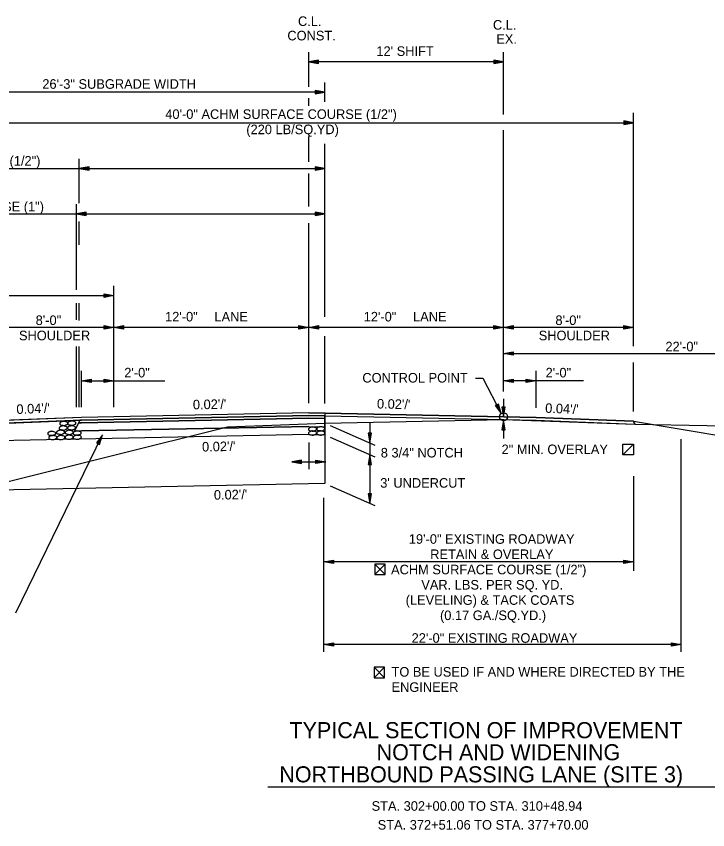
# Model space of a CAD drawing. Extents: x 1398565 to 1398920, y 1968324 to 1968581.
# Drawn here: x 1398824.7 to 1398867.3, y 1968530.5 to 1968580.6 of the extents above; entities that cross this region are included whole.
import ezdxf

# ---------------------------------------------------------------- set-up
doc = ezdxf.new("R2010")
doc.units = 0
for name, color, linetype in [('1', 7, 'Continuous'), ('10', 7, 'Continuous'), ('19', 7, 'Continuous'), ('42', 7, 'Continuous'), ('7', 7, 'Continuous'), ('Level 1', 7, 'Continuous'), ('Level 9', 7, 'Continuous')]:
    doc.layers.add(name, color=color, linetype=linetype)

# ---------------------------------------------------------------- blocks, each defined once
blk = doc.blocks.new('ROCKS')
at = {"layer": '1'}
blk.add_spline([(0.013, 0.06), (0.053, 0.053), (0.107, 0.033), (0.133, 0.013), (0.133, -0.007), (0.12, -0.033), (0.107, -0.04), (0.073, -0.053), (0.033, -0.067), (0.013, -0.067), (-0.02, -0.06), (-0.06, -0.053), (-0.087, -0.047), (-0.113, -0.02), (-0.113, -0.007), (-0.107, 0.02), (-0.087, 0.033), (-0.067, 0.047), (-0.033, 0.053), (-0.02, 0.06), (0.013, 0.06)], degree=3, dxfattribs=at)

msp = doc.modelspace()

# ---------------------------------------------------------------- linework, layer by layer
at = {"layer": '10'}
for p, q in [((1398846.824, 1968546.876), (1398847.465, 1968546.235)), ((1398847.465, 1968546.876), (1398846.824, 1968546.235)), ((1398847.205, 1968546.235), (1398847.216, 1968546.235)), ((1398846.781, 1968540.521), (1398847.422, 1968539.88)), ((1398847.422, 1968540.521), (1398846.781, 1968539.88)), ((1398847.163, 1968539.88), (1398847.174, 1968539.88))]:
    msp.add_line(p, q, dxfattribs=at)
for points in [[(1398862.105, 1968554.258), (1398862.746, 1968554.258), (1398862.746, 1968553.617), (1398862.105, 1968553.617)], [(1398862.105, 1968554.258), (1398862.746, 1968554.258), (1398862.105, 1968553.617)]]:
    msp.add_lwpolyline(points, close=True, dxfattribs=at)
for points in [[(1398847.216, 1968546.235), (1398847.465, 1968546.235), (1398847.465, 1968546.876), (1398846.824, 1968546.876), (1398846.824, 1968546.235), (1398847.205, 1968546.235)], [(1398847.174, 1968539.88), (1398847.422, 1968539.88), (1398847.422, 1968540.521), (1398846.781, 1968540.521), (1398846.781, 1968539.88), (1398847.163, 1968539.88)]]:
    msp.add_lwpolyline(points, dxfattribs=at)
at = {"layer": '19'}
for p, q in [((1398843.353, 1968577.927), (1398842.753, 1968577.822)), ((1398854.753, 1968577.822), (1398842.753, 1968577.822)), ((1398842.753, 1968577.822), (1398843.353, 1968577.717)), ((1398843.353, 1968577.872), (1398842.913, 1968577.837)), ((1398842.913, 1968577.807), (1398843.353, 1968577.767)), ((1398843.353, 1968577.717), (1398843.353, 1968577.927)), ((1398854.153, 1968577.928), (1398854.153, 1968577.718)), ((1398854.753, 1968577.822), (1398854.153, 1968577.928)), ((1398854.593, 1968577.837), (1398854.153, 1968577.873)), ((1398854.153, 1968577.718), (1398854.753, 1968577.822)), ((1398854.153, 1968577.768), (1398854.593, 1968577.807)), ((1398843.753, 1968575.35), (1398843.753, 1968576.547)), ((1398843.753, 1968575.947), (1398817.47, 1968575.947)), ((1398843.153, 1968576.053), (1398843.153, 1968575.843)), ((1398843.753, 1968575.947), (1398843.153, 1968576.053)), ((1398843.593, 1968575.962), (1398843.153, 1968575.998)), ((1398843.153, 1968575.843), (1398843.753, 1968575.947)), ((1398843.153, 1968575.893), (1398843.593, 1968575.932)), ((1398862.753, 1968560.298), (1398862.753, 1968574.672)), ((1398822.753, 1968574.072), (1398862.753, 1968574.072)), ((1398862.153, 1968574.178), (1398862.153, 1968573.968)), ((1398862.753, 1968574.072), (1398862.153, 1968574.178)), ((1398862.593, 1968574.087), (1398862.153, 1968574.123)), ((1398862.153, 1968573.968), (1398862.753, 1968574.072)), ((1398862.153, 1968574.018), (1398862.593, 1968574.057)), ((1398843.753, 1968562.114), (1398843.753, 1968572.76)), ((1398828.626, 1968569.111), (1398828.626, 1968571.85)), ((1398829.226, 1968571.355), (1398828.626, 1968571.25)), ((1398829.226, 1968571.3), (1398828.786, 1968571.265)), ((1398829.226, 1968571.145), (1398829.226, 1968571.355)), ((1398843.153, 1968571.355), (1398843.153, 1968571.145)), ((1398843.753, 1968571.25), (1398843.153, 1968571.355)), ((1398843.593, 1968571.265), (1398843.153, 1968571.3)), ((1398810.228, 1968571.25), (1398843.753, 1968571.25)), ((1398828.626, 1968571.25), (1398829.226, 1968571.145)), ((1398828.786, 1968571.235), (1398829.226, 1968571.195)), ((1398843.153, 1968571.145), (1398843.753, 1968571.25)), ((1398843.153, 1968571.195), (1398843.593, 1968571.235)), ((1398828.455, 1968563.783), (1398828.455, 1968569.052)), ((1398811.73, 1968568.452), (1398843.753, 1968568.452)), ((1398829.055, 1968568.557), (1398828.455, 1968568.452)), ((1398828.455, 1968568.452), (1398829.055, 1968568.347)), ((1398829.055, 1968568.502), (1398828.615, 1968568.467)), ((1398828.615, 1968568.437), (1398829.055, 1968568.397)), ((1398829.055, 1968568.347), (1398829.055, 1968568.557)), ((1398843.153, 1968568.558), (1398843.153, 1968568.348)), ((1398843.753, 1968568.452), (1398843.153, 1968568.558)), ((1398843.593, 1968568.467), (1398843.153, 1968568.503)), ((1398843.153, 1968568.348), (1398843.753, 1968568.452)), ((1398843.153, 1968568.398), (1398843.593, 1968568.437)), ((1398828.626, 1968566.544), (1398828.626, 1968567.985)), ((1398830.753, 1968556.554), (1398830.753, 1968564.017)), ((1398806.753, 1968563.417), (1398830.753, 1968563.417)), ((1398830.153, 1968563.312), (1398830.153, 1968563.522)), ((1398830.153, 1968563.522), (1398830.753, 1968563.417)), ((1398830.153, 1968563.467), (1398830.593, 1968563.432)), ((1398830.753, 1968563.417), (1398830.153, 1968563.312)), ((1398830.593, 1968563.402), (1398830.153, 1968563.362)), ((1398828.455, 1968561.935), (1398828.455, 1968562.956)), ((1398828.626, 1968561.882), (1398828.626, 1968562.956)), ((1398830.753, 1968561.463), (1398817.47, 1968561.463)), ((1398830.153, 1968561.358), (1398830.153, 1968561.568)), ((1398830.153, 1968561.568), (1398830.753, 1968561.463)), ((1398830.153, 1968561.513), (1398830.593, 1968561.478)), ((1398830.753, 1968561.463), (1398830.153, 1968561.358)), ((1398830.593, 1968561.448), (1398830.153, 1968561.408)), ((1398830.753, 1968561.463), (1398831.353, 1968561.568)), ((1398831.353, 1968561.358), (1398830.753, 1968561.463)), ((1398842.753, 1968561.463), (1398830.753, 1968561.463)), ((1398830.913, 1968561.478), (1398831.353, 1968561.513)), ((1398831.353, 1968561.408), (1398830.913, 1968561.448)), ((1398831.353, 1968561.568), (1398831.353, 1968561.358)), ((1398842.153, 1968561.358), (1398842.153, 1968561.568)), ((1398842.153, 1968561.568), (1398842.753, 1968561.463)), ((1398842.153, 1968561.513), (1398842.593, 1968561.478)), ((1398842.753, 1968561.463), (1398842.153, 1968561.358)), ((1398842.593, 1968561.448), (1398842.153, 1968561.408)), ((1398842.753, 1968561.463), (1398843.353, 1968561.568)), ((1398843.353, 1968561.358), (1398842.753, 1968561.463)), ((1398854.753, 1968561.463), (1398842.753, 1968561.463)), ((1398842.913, 1968561.478), (1398843.353, 1968561.513)), ((1398843.353, 1968561.408), (1398842.913, 1968561.448)), ((1398843.353, 1968561.568), (1398843.353, 1968561.358)), ((1398854.153, 1968561.358), (1398854.153, 1968561.568)), ((1398854.153, 1968561.568), (1398854.753, 1968561.463)), ((1398854.153, 1968561.513), (1398854.593, 1968561.478)), ((1398854.753, 1968561.463), (1398854.153, 1968561.358)), ((1398854.593, 1968561.448), (1398854.153, 1968561.408)), ((1398854.753, 1968561.463), (1398855.353, 1968561.568)), ((1398855.353, 1968561.358), (1398854.753, 1968561.463)), ((1398862.753, 1968561.463), (1398854.753, 1968561.463)), ((1398854.913, 1968561.478), (1398855.353, 1968561.513)), ((1398855.353, 1968561.408), (1398854.913, 1968561.448)), ((1398855.353, 1968561.568), (1398855.353, 1968561.358)), ((1398862.153, 1968561.358), (1398862.153, 1968561.568)), ((1398862.153, 1968561.568), (1398862.753, 1968561.463)), ((1398862.153, 1968561.513), (1398862.593, 1968561.478)), ((1398862.753, 1968561.463), (1398862.153, 1968561.358)), ((1398862.593, 1968561.448), (1398862.153, 1968561.408)), ((1398843.753, 1968556.774), (1398843.753, 1968560.916)), ((1398828.455, 1968556.554), (1398828.455, 1968560.285)), ((1398828.626, 1968556.554), (1398828.626, 1968560.285)), ((1398854.753, 1968559.857), (1398855.353, 1968559.962)), ((1398854.753, 1968559.857), (1398876.753, 1968559.857)), ((1398855.353, 1968559.752), (1398854.753, 1968559.857)), ((1398854.913, 1968559.872), (1398855.353, 1968559.907)), ((1398855.353, 1968559.802), (1398854.913, 1968559.842)), ((1398855.353, 1968559.962), (1398855.353, 1968559.752)), ((1398862.753, 1968556.282), (1398862.753, 1968559.302)), ((1398828.753, 1968556.554), (1398828.753, 1968558.775)), ((1398856.753, 1968556.514), (1398856.753, 1968558.775)), ((1398828.753, 1968558.175), (1398829.353, 1968558.28)), ((1398829.353, 1968558.28), (1398829.353, 1968558.07)), ((1398830.153, 1968558.07), (1398830.153, 1968558.28)), ((1398830.153, 1968558.28), (1398830.753, 1968558.175)), ((1398854.753, 1968558.175), (1398855.353, 1968558.28)), ((1398855.353, 1968558.28), (1398855.353, 1968558.07)), ((1398856.153, 1968558.07), (1398856.153, 1968558.28)), ((1398856.153, 1968558.28), (1398856.753, 1968558.175)), ((1398828.753, 1968558.175), (1398833.9, 1968558.175)), ((1398829.353, 1968558.07), (1398828.753, 1968558.175)), ((1398828.913, 1968558.19), (1398829.353, 1968558.225)), ((1398829.353, 1968558.12), (1398828.913, 1968558.16)), ((1398830.153, 1968558.225), (1398830.593, 1968558.19)), ((1398830.753, 1968558.175), (1398830.153, 1968558.07)), ((1398830.593, 1968558.16), (1398830.153, 1968558.12)), ((1398859.679, 1968558.175), (1398854.753, 1968558.175)), ((1398855.353, 1968558.07), (1398854.753, 1968558.175)), ((1398854.913, 1968558.19), (1398855.353, 1968558.225)), ((1398855.353, 1968558.12), (1398854.913, 1968558.16)), ((1398856.153, 1968558.225), (1398856.593, 1968558.19)), ((1398856.753, 1968558.175), (1398856.153, 1968558.07)), ((1398856.593, 1968558.16), (1398856.153, 1968558.12)), ((1398854.43, 1968556.739), (1398854.244, 1968556.644)), ((1398854.607, 1968556.157), (1398854.43, 1968556.739)), ((1398854.753, 1968557.062), (1398854.753, 1968555.954)), ((1398854.244, 1968556.644), (1398854.607, 1968556.157)), ((1398854.286, 1968556.662), (1398854.521, 1968556.293)), ((1398854.545, 1968556.303), (1398854.384, 1968556.711)), ((1398854.858, 1968556.554), (1398854.648, 1968556.554)), ((1398854.648, 1968556.554), (1398854.753, 1968555.954)), ((1398854.703, 1968556.554), (1398854.738, 1968556.114)), ((1398854.753, 1968555.954), (1398854.858, 1968556.554)), ((1398854.768, 1968556.114), (1398854.808, 1968556.554)), ((1398828.753, 1968555.747), (1398822.668, 1968555.503)), ((1398828.753, 1968555.914), (1398822.753, 1968555.674)), ((1398828.668, 1968555.744), (1398828.583, 1968555.573)), ((1398842.753, 1968556.194), (1398828.753, 1968555.914)), ((1398842.753, 1968556.027), (1398828.753, 1968555.747)), ((1398842.753, 1968555.86), (1398828.753, 1968555.58)), ((1398842.753, 1968556.194), (1398856.753, 1968555.914)), ((1398842.753, 1968556.027), (1398856.753, 1968555.747)), ((1398842.753, 1968555.86), (1398843.753, 1968555.84)), ((1398843.753, 1968555.84), (1398842.753, 1968555.86)), ((1398843.753, 1968556.174), (1398843.753, 1968554.548)), ((1398843.753, 1968555.34), (1398843.753, 1968555.84)), ((1398854.753, 1968555.745), (1398854.648, 1968555.145)), ((1398854.858, 1968555.145), (1398854.753, 1968555.745)), ((1398854.753, 1968555.745), (1398854.753, 1968554.624)), ((1398856.753, 1968555.914), (1398862.753, 1968555.674)), ((1398856.753, 1968555.747), (1398862.838, 1968555.503)), ((1398828.583, 1968555.573), (1398828.328, 1968555.063)), ((1398828.583, 1968555.573), (1398828.328, 1968555.063)), ((1398828.753, 1968555.58), (1398828.583, 1968555.573)), ((1398842.753, 1968555.36), (1398828.753, 1968555.08)), ((1398842.753, 1968555.36), (1398843.753, 1968555.34)), ((1398842.753, 1968555.36), (1398843.753, 1968555.34)), ((1398844.083, 1968555.421), (1398846.826, 1968554.212)), ((1398846.524, 1968555.624), (1398846.524, 1968554.348)), ((1398854.738, 1968555.585), (1398854.703, 1968555.145)), ((1398854.808, 1968555.145), (1398854.768, 1968555.585)), ((1398862.753, 1968555.674), (1398876.753, 1968553.34)), ((1398862.753, 1968555.674), (1398862.838, 1968555.503)), ((1398842.753, 1968554.858), (1398817.47, 1968554.352)), ((1398824.713, 1968543.872), (1398830.051, 1968554.837)), ((1398828.753, 1968555.08), (1398828.328, 1968555.063)), ((1398830.051, 1968554.837), (1398829.687, 1968554.349)), ((1398829.874, 1968554.256), (1398830.051, 1968554.837)), ((1398842.753, 1968554.858), (1398843.753, 1968554.838)), ((1398846.629, 1968554.948), (1398846.419, 1968554.948)), ((1398846.419, 1968554.948), (1398846.524, 1968554.348)), ((1398846.474, 1968554.948), (1398846.509, 1968554.508)), ((1398846.524, 1968554.348), (1398846.629, 1968554.948)), ((1398846.539, 1968554.508), (1398846.579, 1968554.948)), ((1398854.648, 1968555.145), (1398854.858, 1968555.145)), ((1398829.687, 1968554.349), (1398829.874, 1968554.256)), ((1398829.969, 1968554.701), (1398829.736, 1968554.327)), ((1398829.83, 1968554.279), (1398829.994, 1968554.688)), ((1398843.753, 1968554.548), (1398843.753, 1968551.838)), ((1398844.083, 1968554.692), (1398846.826, 1968553.483)), ((1398846.524, 1968554.348), (1398846.524, 1968550.616)), ((1398865.69, 1968541.466), (1398865.69, 1968554.576)), ((1398846.524, 1968553.616), (1398846.419, 1968553.016)), ((1398846.509, 1968553.456), (1398846.474, 1968553.016)), ((1398846.629, 1968553.016), (1398846.524, 1968553.616)), ((1398846.579, 1968553.016), (1398846.539, 1968553.456)), ((1398846.419, 1968553.016), (1398846.629, 1968553.016)), ((1398862.753, 1968552.288), (1398862.753, 1968546.467)), ((1398843.753, 1968551.838), (1398804.922, 1968551.061)), ((1398844.083, 1968551.692), (1398846.826, 1968550.483)), ((1398843.69, 1968541.466), (1398843.69, 1968550.967)), ((1398846.629, 1968551.216), (1398846.419, 1968551.216)), ((1398846.419, 1968551.216), (1398846.524, 1968550.616)), ((1398846.474, 1968551.216), (1398846.509, 1968550.776)), ((1398846.524, 1968550.616), (1398846.629, 1968551.216)), ((1398846.539, 1968550.776), (1398846.579, 1968551.216)), ((1398843.69, 1968547.023), (1398844.29, 1968547.128)), ((1398844.29, 1968546.918), (1398843.69, 1968547.023)), ((1398862.753, 1968547.023), (1398843.69, 1968547.023)), ((1398843.85, 1968547.038), (1398844.29, 1968547.073)), ((1398844.29, 1968546.968), (1398843.85, 1968547.008)), ((1398844.29, 1968547.128), (1398844.29, 1968546.918)), ((1398862.153, 1968546.918), (1398862.153, 1968547.128)), ((1398862.153, 1968547.128), (1398862.753, 1968547.023)), ((1398862.153, 1968547.073), (1398862.593, 1968547.038)), ((1398862.753, 1968547.023), (1398862.153, 1968546.918)), ((1398862.593, 1968547.008), (1398862.153, 1968546.968)), ((1398843.69, 1968541.928), (1398844.29, 1968542.033)), ((1398865.69, 1968541.928), (1398843.69, 1968541.928)), ((1398844.29, 1968541.823), (1398843.69, 1968541.928)), ((1398843.85, 1968541.943), (1398844.29, 1968541.978)), ((1398844.29, 1968541.873), (1398843.85, 1968541.913)), ((1398844.29, 1968542.033), (1398844.29, 1968541.823)), ((1398865.09, 1968541.823), (1398865.09, 1968542.033)), ((1398865.09, 1968542.033), (1398865.69, 1968541.928)), ((1398865.09, 1968541.978), (1398865.53, 1968541.943)), ((1398865.69, 1968541.928), (1398865.09, 1968541.823)), ((1398865.53, 1968541.913), (1398865.09, 1968541.873)), ((1398840.237, 1968533.167), (1398869.217, 1968533.167))]:
    msp.add_line(p, q, dxfattribs=at)
for points in [[(1398853.028, 1968558.334), (1398853.474, 1968558.334), (1398854.607, 1968556.157)], [(1398842.753, 1968555.86), (1398828.753, 1968555.58), (1398828.583, 1968555.573)], [(1398828.328, 1968555.063), (1398828.753, 1968555.08), (1398842.753, 1968555.36)]]:
    msp.add_lwpolyline(points, dxfattribs=at)
for points in [[(1398822.671, 1968555.508), (1398828.753, 1968555.747), (1398842.753, 1968556.027), (1398856.753, 1968555.747), (1398862.838, 1968555.503), (1398862.753, 1968555.674), (1398856.753, 1968555.914), (1398842.753, 1968556.194), (1398828.753, 1968555.914), (1398822.753, 1968555.674)], [(1398828.668, 1968555.744), (1398828.583, 1968555.573), (1398828.753, 1968555.58), (1398842.753, 1968555.86), (1398843.753, 1968555.84), (1398843.753, 1968556.007), (1398842.753, 1968556.027), (1398828.753, 1968555.747)]]:
    msp.add_lwpolyline(points, close=True, dxfattribs=at)
at = {"layer": '42'}
for p, q in [((1398842.753, 1968554.36), (1398842.753, 1968552.728)), ((1398842.306, 1968553.285), (1398841.706, 1968553.18)), ((1398842.306, 1968553.23), (1398841.866, 1968553.195)), ((1398842.306, 1968553.075), (1398842.306, 1968553.285)), ((1398843.201, 1968553.075), (1398843.201, 1968553.285)), ((1398843.201, 1968553.285), (1398843.801, 1968553.18)), ((1398843.201, 1968553.23), (1398843.641, 1968553.195)), ((1398841.706, 1968553.18), (1398842.306, 1968553.075)), ((1398841.706, 1968553.18), (1398843.801, 1968553.18)), ((1398841.866, 1968553.165), (1398842.306, 1968553.125)), ((1398843.801, 1968553.18), (1398843.201, 1968553.075)), ((1398843.641, 1968553.165), (1398843.201, 1968553.125))]:
    msp.add_line(p, q, dxfattribs=at)
for points in [[(1398843.753, 1968555.567), (1398854.753, 1968555.787)], [(1398854.753, 1968555.787), (1398862.838, 1968555.503), (1398871.753, 1968555.327), (1398880.608, 1968552.866), (1398885.689, 1968553.408), (1398902.506, 1968553.319)], [(1398766.812, 1968548.312), (1398812.323, 1968548.993), (1398816.74, 1968550.093), (1398837.753, 1968555.327), (1398843.753, 1968555.567)]]:
    msp.add_lwpolyline(points, dxfattribs=at)
at = {"layer": '7'}
for p, q in [((1398842.753, 1968576.288), (1398842.753, 1968578.422)), ((1398854.753, 1968574.585), (1398854.753, 1968578.422)), ((1398842.753, 1968575.109), (1398842.753, 1968575.581)), ((1398854.753, 1968557.519), (1398854.753, 1968573.616)), ((1398842.753, 1968571.652), (1398842.753, 1968573.223)), ((1398842.753, 1968568.902), (1398842.753, 1968570.945)), ((1398842.753, 1968556.794), (1398842.753, 1968567.88))]:
    msp.add_line(p, q, dxfattribs=at)
at = {"layer": 'Level 9'}
msp.add_circle((1398854.753, 1968555.954), 0.25, dxfattribs=at)

# ---------------------------------------------------------------- block references
at = {"layer": 'Level 1', "xscale": 2.011654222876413, "yscale": 2.011654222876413, "rotation": 1.8263814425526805}
for p in [(1398827.622, 1968555.271), (1398827.648, 1968555.55), (1398828.133, 1968555.282), (1398828.147, 1968555.565), (1398842.974, 1968555.202), (1398843.472, 1968555.217), (1398826.911, 1968554.935), (1398826.97, 1968554.68), (1398827.454, 1968555.005), (1398827.474, 1968554.679), (1398827.98, 1968554.7), (1398827.987, 1968555.001), (1398828.478, 1968554.957), (1398828.484, 1968554.7), (1398842.974, 1968554.96), (1398843.478, 1968554.96)]:
    msp.add_blockref('ROCKS', p, dxfattribs=at)

# ---------------------------------------------------------------- texts
at = {"layer": '10'}
for s, height, p in [("12' SHIFT", 0.59, (1398846.924, 1968578.186)), ('12\'-0" ', 0.59, (1398833.911, 1968561.826)), ('LANE', 0.59, (1398836.949, 1968561.826)), ('12\'-0" ', 0.59, (1398846.141, 1968561.826)), ('LANE', 0.59, (1398849.179, 1968561.826)), ('8\'-0" ', 0.59, (1398825.94, 1968561.608)), ('8\'-0" ', 0.59, (1398857.945, 1968561.607)), ('SHOULDER', 0.59, (1398824.913, 1968560.668)), ('SHOULDER', 0.59, (1398856.918, 1968560.667)), ('22\'-0"', 0.59, (1398864.718, 1968559.985)), ('2\'-0"', 0.59, (1398831.396, 1968558.378)), ('2\'-0"', 0.59, (1398857.341, 1968558.378)), ('CONTROL POINT', 0.59001, (1398846.058, 1968558.062)), ('2" MIN. OVERLAY', 0.59001, (1398854.629, 1968553.653)), ('8 3/4" NOTCH', 0.59001, (1398847.192, 1968553.447)), ("3' UNDERCUT", 0.59001, (1398847.159, 1968551.585)), ('19\'-0" EXISTING ROADWAY', 0.59001, (1398848.92, 1968548.13)), ('RETAIN & OVERLAY', 0.59001, (1398850.235, 1968547.19)), ('ACHM SURFACE COURSE (1/2")', 0.59001, (1398847.824, 1968546.25)), ('VAR. LBS. PER SQ. YD.', 0.59001, (1398849.687, 1968545.31)), ('(LEVELING) & TACK COATS', 0.59001, (1398848.725, 1968544.37)), ('(0.17 GA./SQ.YD.)', 0.59001, (1398850.839, 1968543.43)), ('22\'-0" EXISTING ROADWAY', 0.59001, (1398849.09, 1968542.032)), ('TO BE USED IF AND WHERE DIRECTED BY THE ', 0.59001, (1398847.854, 1968539.947)), ('ENGINEER', 0.59, (1398847.854, 1968539.007)), ('STA. 302+00.00 TO STA. 310+48.94', 0.59001, (1398846.627, 1968531.683)), ('STA. 372+51.06 TO STA. 377+70.00', 0.59001, (1398847.001, 1968530.524))]:
    msp.add_text(s, height=height, rotation=360, dxfattribs=at).set_placement(p)
at = {"layer": '19'}
for p in [(1398842.093, 1968580.028), (1398854.098, 1968579.801)]:
    msp.add_text('C.L.', height=0.59, dxfattribs=at).set_placement(p)
for s, height, rotation, p in [('CONST.', 0.59, 360, (1398841.44, 1968579.14)), ('EX.', 0.59, 360, (1398854.304, 1968578.934)), ("0.04'/'", 0.59, 2.2906, (1398824.766, 1968556.123)), ("0.02'/'", 0.59, 1.1458, (1398835.628, 1968556.407)), ("0.02'/'", 0.59, 358.8542, (1398846.952, 1968556.466)), ("0.04'/'", 0.59, 357.7094, (1398857.305, 1968556.203)), ("0.02'/'", 0.59, 1.1458, (1398836.191, 1968553.811)), ("0.02'/'", 0.59, 1.1458, (1398836.92, 1968550.844)), ('TYPICAL SECTION OF IMPROVEMENT', 0.98999, 360, (1398841.571, 1968536.155)), ('NOTCH AND WIDENING', 0.98999, 360, (1398846.934, 1968534.794)), ('NORTHBOUND PASSING LANE (SITE 3)', 0.98999, 360, (1398840.943, 1968533.433))]:
    msp.add_text(s, height=height, rotation=rotation, dxfattribs=at).set_placement(p)
at = {"layer": '42'}
for s, p in [('26\'-3" SUBGRADE WIDTH', (1398826.35, 1968576.16)), ('40\'-0" ACHM SURFACE COURSE (1/2")', (1398833.922, 1968574.303)), ('(220 LB/SQ.YD)', (1398838.911, 1968573.363)), ('15\'-1 1/2" ACHM SURFACE COURSE (1/2")', (1398810.661, 1968571.429)), ('15\'-3 1/2" ACHM BINDER COURSE (1")', (1398812.326, 1968568.61))]:
    msp.add_text(s, height=0.59001, rotation=360, dxfattribs=at).set_placement(p)

doc.saveas('drawing.dxf')
